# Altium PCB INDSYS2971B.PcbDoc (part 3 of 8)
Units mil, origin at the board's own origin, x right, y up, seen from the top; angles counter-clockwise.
Board outline 6450 x 5820 mil, 6 copper layers (Top Layer, Int1 (PGND), Int2 (AGND), Int3 (Signal), Int4 (PGND), Bottom Layer), stack 70.536 mil thick; 787 components, 431 nets, 2530 pads, 2497 vias.
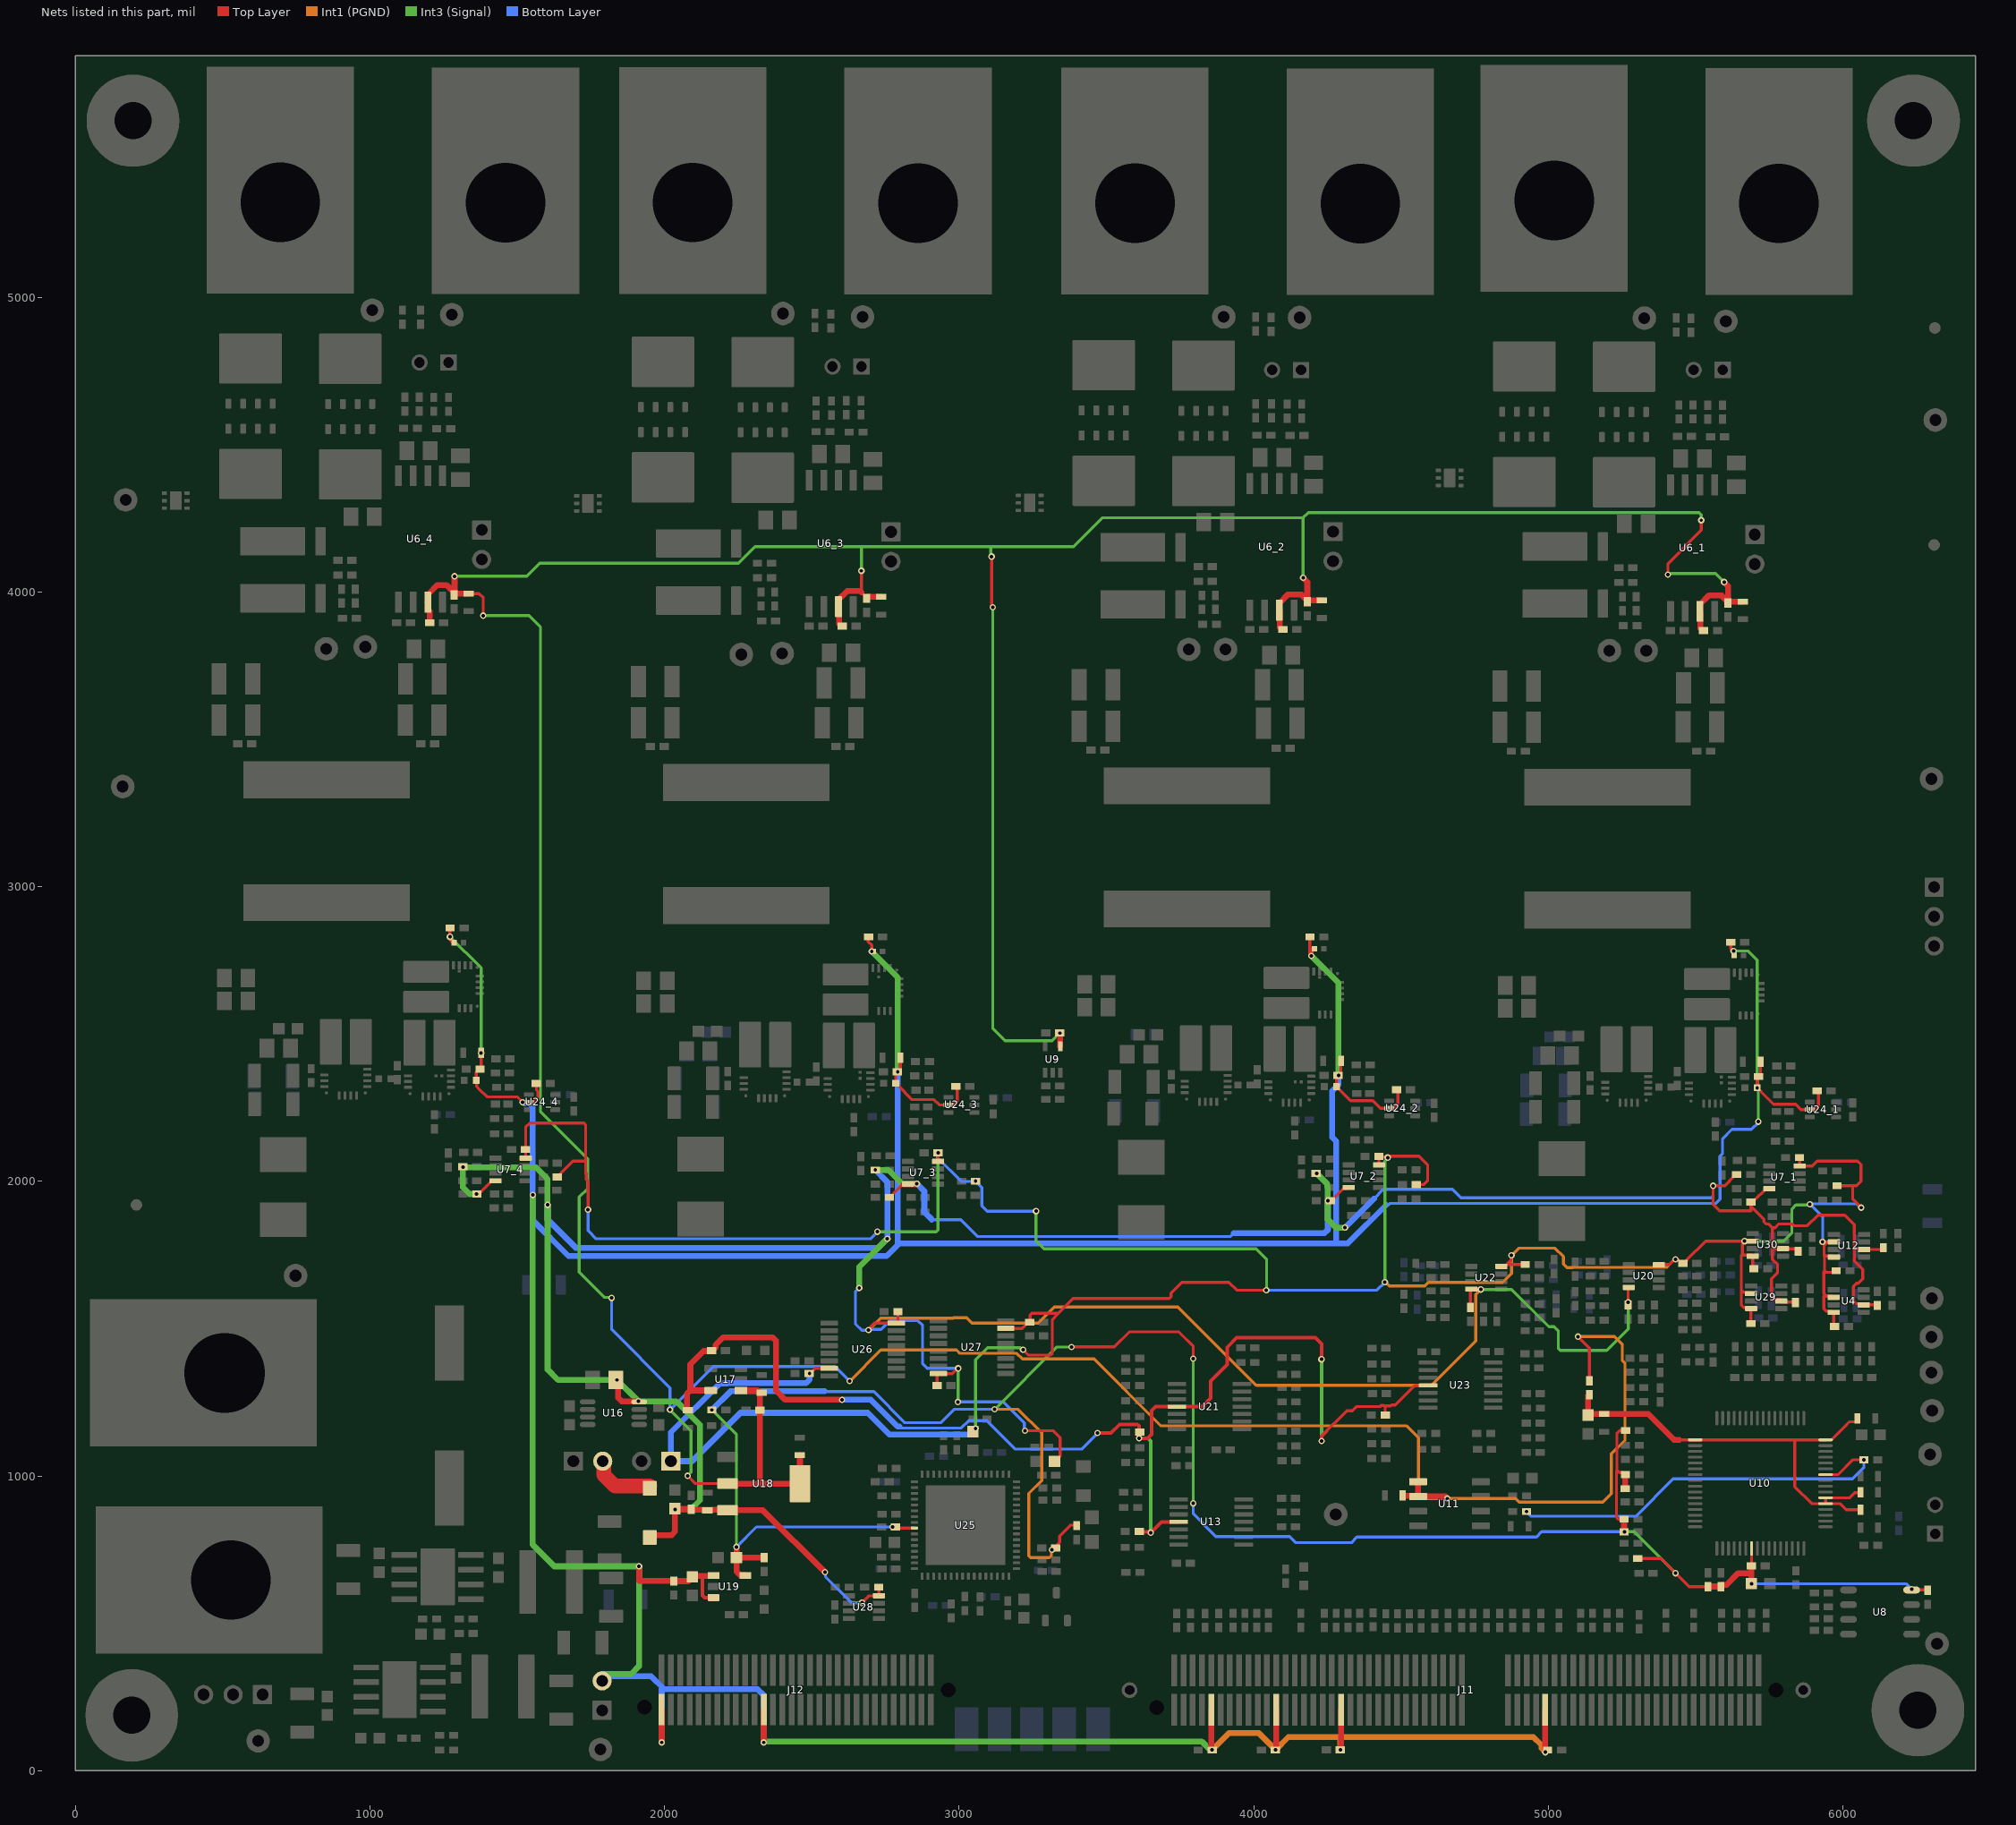
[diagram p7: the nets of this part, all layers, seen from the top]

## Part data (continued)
C41 C70 C95: library part CMP-0006644-2, "CAP, CERM, 0.015 uF, 16 V, +/- 10%, X7R, 0402", Cap_Case=0402, Manufacturer=MuRata, Supplier Part Number 1=490-1314-1-ND, TempCo=X7R, Tolerance_%=10%, Value1=Unknown, Value2=16V, ValueDisplayed=0.015uF
C42 C48 C49 C50 C51 C52 C53 C54 C110 C111 C112 C113: library part CMP-0006611-2, "CAP, CERM, 4700 pF, 25 V, +/- 10%, X5R, 0402", Cap_Case=0402, Manufacturer=MuRata, Supplier Part Number 1=GRM155R61E472KA01D-ND, TempCo=X5R, Tolerance_%=10%, Value1=Unknown, Value2=25V, ValueDisplayed=4700pF
C43 C56 C59 C63 C82 C86 C88 C92 C94 C116 C122: library part CMP-0007344-5, "CAP, CERM, 10 uF, 25 V, +/- 20%, X5R, 0603", Cap_Case=0603, Manufacturer=MuRata, Supplier Part Number 1=490-7202-1-ND, TempCo=X5R, Tolerance_%=20%, Value1=Unknown, Value2=25V, ValueDisplayed=10uF
C87: library part CMP-0076705-3, "CAP TANT POLY 2.2UF 10V 0603", Cap_Case=1.6x0.8x0.8mm, Manufacturer="KYOCERA AVX", TempCo=X7R, Tolerance_%=20%, Value2=10V, ValueDisplayed=2.2uF
D1 D2 D3: library part CMP-0002894-2, "LED, Green, SMD", Color=green, Manufacturer="Wurth Elektronik", Value1=W, Value2=2V
D4_1 D4_2 D4_3 D4_4 D5_1 D5_2 D5_3 D5_4: library part CMP-0028594-3, "Diode, Schottky, 40 V, 0.35 A, SOD-523", Manufacturer="Diodes Inc.", Value1=0.35A, Value2=0.65V
D6: library part CMP-0002829-3, "LED, Red, SMD", Color=red, Manufacturer=Lite-On, Value1=W, Value2=2V
D7: library part CMP-0082437-2, "LED, Blue, SMD", Color=Blue, Manufacturer=Lite-On, Power_TotalModule=76mW, Value1=0.076W, Value2=3.3V
F1_1 F1_2 F1_3 F1_4: library part CMP-0003569-2, "Fuse, 15 A, SMD", Irating_A=15A
FID1 FID2 FID3: library part CMP-0077181-1, "Fiducial mark.  There is nothing to buy or mount.", Manufacturer=N/A
H1 H2 H3 H4: library part CMP-0003617-1, "Machine Screw, Round, #4-40 x 1/4, Nylon, Philips panhead", Manufacturer="B&F Fastener Supply", Supplier Part Number 1=H542-ND
H5 H6 H7 H8: library part CMP-0003610-1, "Standoff, Hex, 0.5\"L #4-40 Nylon", Manufacturer=Keystone, Supplier Part Number 1=36-1902C-ND
J1 J2 J7_1 J7_2 J7_3 J7_4 J8_1 J8_2 J8_3 J8_4: library part CMP-0055387-2, "Standard Banana Jack, Uninsulated, 15A", Manufacturer="Cinch Connectivity", Supplier Part Number 1=J147-ND
J3 J10_1 J10_2 J10_3 J10_4: library part CMP-0075228-1, "Header (Shrouded), 2.5mm, 2x1, Tin, TH", Color=White, Current_A=3A, Manufacturer="JST Manufacturing", Supplier Part Number 1=455-1611-ND, Voltage_V=250V
J6 J16: library part CMP-0075484-1, "Header, 100mil, 3x1, Gold, TH", Manufacturer=Samtec, Supplier Part Number 1=HTSW-103-07-G-S-ND
J9_1 J9_2 J9_3 J9_4 J14 J15 J17: library part CMP-0075483-1, "Header, 100mil, 2x1, Gold, TH", Manufacturer=Samtec, Supplier Part Number 1=SAM8736-ND
J11: library part CMP-0003814-2, "C2000 controlCARD-120HSEC connector, SMT", Manufacturer=Samtec
J12: library part CMP-0003859-2, "C2000 controlCARD-180HSEC (60-pin addon) connector, SMT", Manufacturer=Samtec
L1_1 L1_2 L1_3 L1_4: library part CMP-0060973-1, "Inductor, Shielded, Composite, 1 uH, 57.5 A, 0.000929 ohm, SMD", Manufacturer=Coilcraft, Value1="0.000929 ohm", Value2=57.5A, ValueDisplayed=1uH
L2 L3: library part CMP-0095453-1, "22 µH Shielded Inductor 5.8 A 46.9mOhm Max Nonstandard", Digikey Part Number=2457-XGL6060-223MEC-ND, Manufacturer=Coilcraft, Operating Temperature Range=to, Self Resonant Frequency=9MHz, Test Frequency=1MHz, Tolerance_%=20%
L4: library part CMP-0003369-1, "Ferrite Bead, 1000 ohm @ 100 MHz, 1.5 A, 1806", Manufacturer=MuRata, Supplier Part Number 1=490-1061-1-ND, Value1="0.09 ohm", Value2=1.5A, ValueDisplayed="1000 ohm"
LBL1: library part CMP-0003625-1, "Thermal Transfer Printable Labels, 0.650\" W x 0.200\" H - 10,000 per roll", Manufacturer=Brady, Supplier Part Number 1=97C5133
Logo1: library part CMP-0074844-1
Logo2: library part CMP-0074838-1, "Texas Instrument Corporate Signature"
Logo3: library part CMP-0074847-1, "FCC_disclaimer"
Logo4: library part CMP-0074769-3, Manufacturer="Texas Instruments"
Logo5 Logo6 Logo7 Logo8: library part CMP-0074837-2, "IEC 61010-1 Hot Surface Warning", Manufacturer="Texas Instruments"
NT1_1 NT1_2 NT1_3 NT1_4 NT2_1 NT2_2 NT2_3 NT2_4: library part CMP-0078142-6, "Single point connection between nets.", Manufacturer=N/A
Q1_1 Q1_2 Q1_3 Q1_4 Q2_1 Q2_2 Q2_3 Q2_4 Q3_1 Q3_2 Q3_3 Q3_4 Q4_1 Q4_2 Q4_3 Q4_4: library part CMP-0000274-2, "MOSFET, N-CH, 25 V, 100 A, DNK0008A (VSON-CLIP-8)", Alternate Manufacturer=None, Manufacturer="Texas Instruments", Supplier Part Number 1=CSD16570Q5B-ND, Value1=0, Value2="192 nC"
Q5: library part CMP-0000769-1, "MOSFET, N-CH, 60 V, 0.17 A, SOT-23", Alternate Manufacturer=None, Manufacturer="Diodes Inc.", Supplier Part Number 1=2N7002-FDICT-ND, Value1=7, Value2="223 nC"
R1_1 R1_2 R1_3 R1_4 R9_1 R9_2 R9_3 R9_4 R14_1 R14_2 R14_3 R14_4: library part CMP-02407-004899-1, "RES Thick Film, 3.01Ω, 1%, 0.063W, 200ppm/°C, 0402", Case Code (Imperial)=0402, Case Code (Metric)=1005, Max Operating Temperature=155°C, Max Power Dissipation=63mW, Min Operating Temperature=-55°C, Package Quantity=10000, Resistance=3.01R, Temperature Coefficient=200ppm/°C, Tolerance=1%, Voltage Rating=50V
R2_1 R2_2 R2_3 R2_4: library part CMP-0086415-1, "RESISTOR - ISA-WELD SHUNT, 0.000", Manufacturer=Vishay, Power_W=9W, TempCo=75ppm/°C, Tolerance_%=1%
R3_1 R3_2 R3_3 R3_4: library part CMP-0020448-3, "RES, 10, 5%, 0.125 W, AEC-Q200 Grade 0, 0805", Manufacturer=Vishay-Dale, Power_W=125mW, Supplier Part Number 1=541-10ACT-ND, TempCo="200 ppm/C", Tolerance_%=5%, Value2=0.125W, Value_Code=10R0, ValueDisplayed=10
R4_1 R4_2 R4_3 R4_4 R5_1 R5_2 R5_3 R5_4 R17_1 R17_2 R17_3 R17_4 R18_1 R18_2 R18_3 R18_4 R20_1 R20_2 R20_3 R20_4 R21_1 R21_2 R21_3 R21_4: library part CMP-0081622-1, "RES, 1.00, 1%, 0.125 W, 0402", Manufacturer="Stackpole Electronics Inc", Power_W=125mW, Supplier Part Number 1=CSR0402FK1R00CT-ND, TempCo="200 ppm/C", Tolerance_%=1%, Value2=0.125W, Value_Code=1R00, ValueDisplayed=1.00
R6_1 R6_2 R6_3 R6_4 R7_1 R7_2 R7_3 R7_4: library part CMP-0020951-3, "RES, 1.00 k, 1%, 0.125 W, AEC-Q200 Grade 0, 0805", Manufacturer=Vishay-Dale, Power_W=125mW, Supplier Part Number 1=541-1.00KCCT-ND, TempCo="100 ppm/C", Tolerance_%=1%, Value2=0.125W, Value_Code=1k00, ValueDisplayed=1.00k
R8 R15_1 R15_2 R15_3 R15_4 R16 R19_1 R19_2 R19_3 R19_4 R22_1 R22_2 R22_3 R22_4 R36 R37 R38 R39 R40 R41 R42 R43 R44 R45 R46 R48 R50 R55 R56 R70 R88 R101 R106 R113 R117 R139 R151 R162 R175 R199 R200 R201 R202 R203 R204 R205 R206 R210 R211 R212 R213 R214 R215 R216 R218 R220 R223 R225 R227 R235 R236 R237 R238 R239 R240 R242 R244 R245 R246 R247 R248 R249 R252 R253 R255 R256 R257 R258 R259 R260: library part CMP-0026822-3, "RES, 0, 5%, 0.063 W, AEC-Q200 Grade 0, 0402", Manufacturer=Vishay-Dale, Power_W=63mW, Supplier Part Number 1=541-0.0JCT-ND, TempCo="200 ppm/C", Tolerance_%=5%, Value2=0.063W, Value_Code=0000, ValueDisplayed=0
R10_1 R10_2 R10_3 R10_4 R11_1 R11_2 R11_3 R11_4 R12_1 R12_2 R12_3 R12_4 R13_1 R13_2 R13_3 R13_4 R23_1 R23_2 R23_3 R23_4 R24_1 R24_2 R24_3 R24_4 R28_1 R28_2 R28_3 R28_4 R29_1 R29_2 R29_3 R29_4 R31_1 R31_2 R31_3 R31_4 R32_1 R32_2 R32_3 R32_4 R35_1 R35_2 R35_3 R35_4 R77 R79 R80 R82 R84 R89 R92 R99 R103 R104 R105 R108 R109 R110 R116 R127 R128 R177 R178 R183 R184 R185 R186 R191 R192 R221 R222 R224 R228 R230 R243 R254: library part CMP-0026796-1, "RES, 10.0 k, 0.1%, 0.063 W, 0402", Manufacturer="TT Electronics/IRC", Power_W=63mW, TempCo="10 ppm/C", Tolerance_%=0.1%, Value2=0.063W, Value_Code=10k0, ValueDisplayed=10.0k
R25_1 R25_2 R25_3 R25_4: library part CMP-0025963-3, "RES, 10.0, 1%, 0.063 W, AEC-Q200 Grade 0, 0402", Manufacturer=Vishay-Dale, Power_W=63mW, Supplier Part Number 1=541-10.0LCT-ND, TempCo="100 ppm/C", Tolerance_%=1%, Value2=0.063W, Value_Code=10R0, ValueDisplayed=10.0
R26_1 R26_2 R26_3 R26_4 R33_1 R33_2 R33_3 R33_4: library part CMP-0025992-3, "RES, 12.4 k, 1%, 0.063 W, AEC-Q200 Grade 0, 0402", Manufacturer=Vishay-Dale, Power_W=63mW, Supplier Part Number 1=541-12.4KLCT-ND, TempCo="100 ppm/C", Tolerance_%=1%, Value2=0.063W, Value_Code=12k4, ValueDisplayed=12.4k
R27_1 R27_2 R27_3 R27_4 R34_1 R34_2 R34_3 R34_4: library part CMP-0026745-1, "RES, 100 k, 1%, 0.063 W, 0402", Manufacturer="Samsung Electro-Mechanics", Power_W=63mW, Supplier Part Number 1=1276-3432-1-ND, TempCo="100 ppm/C", Tolerance_%=1%, Value2=0.063W, Value_Code=100k
R30_1 R30_2 R30_3 R30_4 R112 R114 R137 R143 R148 R154 R158 R165 R167 R176: library part CMP-0026162-2, "RES, 20.0 k, 1%, 0.063 W, AEC-Q200 Grade 0, 0402", Manufacturer=Vishay-Dale, Power_W=63mW, Supplier Part Number 1=541-20.0KLCT-ND, TempCo="100 ppm/C", Tolerance_%=1%, Value2=0.063W, Value_Code=20k0, ValueDisplayed=20.0k
R47 R49 R51 R52 R53 R54 R58 R59 R60 R61 R62 R63 R64 R65 R66 R67 R68 R69 R71 R72 R73 R74 R75 R111 R194 R195 R196 R197 R198 R208 R209 R217 R219 R226 R229 R233 R234: library part CMP-0026880-3, "RES, 22, 5%, 0.063 W, AEC-Q200 Grade 0, 0402", Manufacturer=Vishay-Dale, Power_W=63mW, Supplier Part Number 1=541-22JCT-ND, TempCo="200 ppm/C", Tolerance_%=5%, Value2=0.063W, Value_Code=22R0, ValueDisplayed=22
R57 R126 R131 R231 R232 R250 R251: library part CMP-0026770-1, "RES, 1.00 k, 0.1%, 0.063 W, 0402", Manufacturer=Panasonic, Power_W=63mW, Supplier Part Number 1=P1.0KDCCT-ND, TempCo="25 ppm/C", Tolerance_%=0.1%, Value2=0.063W, Value_Code=1k00, ValueDisplayed=1.00k
R76: library part CMP-0026833-3, "RES, 120, 5%, 0.063 W, AEC-Q200 Grade 0, 0402", Manufacturer=Vishay-Dale, Power_W=63mW, Supplier Part Number 1=541-120JCT-ND, TempCo="200 ppm/C", Tolerance_%=5%, Value2=0.063W, Value_Code=120R, ValueDisplayed=120
R78 R81 R83 R85 R86 R87 R90 R91 R93 R94 R95 R96 R97 R98 R100 R102 R133 R138 R144 R149 R155 R161 R166 R173: library part CMP-0026402-2, "RES, 499, 1%, 0.063 W, AEC-Q200 Grade 0, 0402", Manufacturer=Vishay-Dale, Power_W=63mW, Supplier Part Number 1=541-499LCT-ND, TempCo="100 ppm/C", Tolerance_%=1%, Value2=0.063W, Value_Code=499R, ValueDisplayed=499
R107: library part CMP-0026632-2, "RES, 0.22, 1%, 0.125 W, AEC-Q200 Grade 0, 0402", Manufacturer=Panasonic, Power_W=125mW, Supplier Part Number 1=P.22AKCT-ND, TempCo="250 ppm/C", Tolerance_%=1%, Value2=0.125W, Value_Code=R220, ValueDisplayed=0.22
R115: library part CMP-0026158-2, "RES, 200 k, 1%, 0.063 W, AEC-Q200 Grade 0, 0402", Manufacturer=Vishay-Dale, Power_W=63mW, Supplier Part Number 1=541-200KLCT-ND, TempCo="100 ppm/C", Tolerance_%=1%, Value2=0.063W, Value_Code=200k
R118 R179 R180 R181 R182 R187 R188 R189 R190: library part CMP-0026367-2, "RES, 40.2 k, 1%, 0.063 W, AEC-Q200 Grade 0, 0402", Manufacturer=Vishay-Dale, Power_W=63mW, Supplier Part Number 1=541-40.2KLCT-ND, TempCo="100 ppm/C", Tolerance_%=1%, Value2=0.063W, Value_Code=40k2, ValueDisplayed=40.2k
R119: library part CMP-0026720-1, "RES, 69.8 k, 1%, 0.063 W, 0402", Manufacturer=Rohm, Power_W=63mW, TempCo="100 ppm/C", Tolerance_%=1%, Value2=0.063W, Value_Code=69k8, ValueDisplayed=69.8k
R120 R121: library part CMP-0026721-1, "RES, 100 k, 1%, 0.0625 W, 0402", Manufacturer="Yageo America", Power_W=62.5mW, Supplier Part Number 1=311-100KLRCT-ND, TempCo="100 ppm/C", Tolerance_%=1%, Value2=0.0625W, Value_Code=100k
R122 R123: library part CMP-0078779-1, "RES, 10.0 k, 1%, 0.2 W, AEC-Q200 Grade 0, 0402", Manufacturer=Panasonic, Power_W=200mW, Supplier Part Number 1=P17230CT-ND, TempCo="100 ppm/C", Tolerance_%=1%, Value2=0.2W, Value_Code=10k0, ValueDisplayed=10.0k
R124 R125: library part CMP-0022957-5, "RES, 26.1 k, 1%, 0.1 W, 0603", Manufacturer=Yageo, Power_W=100mW, Supplier Part Number 1=311-26.1KHRCT-ND, TempCo="100 ppm/C", Tolerance_%=1%, Value2=0.1W, Value_Code=26k1, ValueDisplayed=26.1k
R129 R130 R132: library part CMP-0094724-1, "Jumper 0.25W, 1/4W Chip Resistor 1206 (3216 Metric) - Thick Film", Digikey Part Number=541-4170-1-ND, Manufacturer=Vishay, Mouser Part Number=71-CRCW12060000Z0EAC, Operating Temperature Range="-55°C to +155°C", Power_W=250mW
R134 R141 R145 R150 R156 R164 R168 R174: library part CMP-0026371-2, "RES, 41.2 k, 1%, 0.063 W, AEC-Q200 Grade 0, 0402", Manufacturer=Vishay-Dale, Power_W=63mW, Supplier Part Number 1=541-41.2KLCT-ND, TempCo="100 ppm/C", Tolerance_%=1%, Value2=0.063W, Value_Code=41k2, ValueDisplayed=41.2k
R135 R136 R140 R142 R146 R147 R152 R153 R157 R159 R160 R163 R169 R170 R171 R172: library part CMP-0026403-2, "RES, 49.9 k, 1%, 0.063 W, AEC-Q200 Grade 0, 0402", Manufacturer=Vishay-Dale, Power_W=63mW, Supplier Part Number 1=541-49.9KLCT-ND, TempCo="100 ppm/C", Tolerance_%=1%, Value2=0.063W, Value_Code=49k9, ValueDisplayed=49.9k
R193_1 R193_2 R193_3 R193_4: library part CMP-0026057-3, "RES, 187, 1%, 0.063 W, AEC-Q200 Grade 0, 0402", Manufacturer=Vishay-Dale, Power_W=63mW, Supplier Part Number 1=541-187LCT-ND, TempCo="100 ppm/C", Tolerance_%=1%, Value2=0.063W, Value_Code=187R, ValueDisplayed=187
R207 R241: library part CMP-0025743-4, "RES, 1.0, 5%, 0.1 W, AEC-Q200 Grade 0, 0603", Manufacturer=Vishay-Dale, Power_W=100mW, Supplier Part Number 1=541-1.0GCT-ND, TempCo="200 ppm/C", Tolerance_%=5%, Value2=0.1W, Value_Code=1R00, ValueDisplayed=1.0
SH-J2 SH-J3 SH-J4 SH-J5: library part CMP-0003761-2, "Shunt, 2.54mm, Gold, Black", Manufacturer="Wurth Elektronik", Supplier Part Number 1=732-2678-ND
T1 T2 T3_1 T3_2 T3_3 T3_4 T4_1 T4_2 T4_3 T4_4: library part CMP-0075010-2, "Terminal 70A Lug", Manufacturer=Panduit, Supplier Part Number 1=CXS70-14-C-ND
TP1 TP3_1 TP3_2 TP3_3 TP3_4 TP5_1 TP5_2 TP5_3 TP5_4 TP11: library part CMP-0055137-2, "Test Point, Miniature, Red, TH", Color=Red, Manufacturer="Keystone Electronics", Supplier Part Number 1=36-5000-ND
TP2 TP4_1 TP4_2 TP4_3 TP4_4 TP6_1 TP6_2 TP6_3 TP6_4 TP9 TP10 TP12 TP13 TP14 TP15 TP16 TP17 TP23: library part CMP-0055138-2, "Test Point, Miniature, Black, TH", Color=Black, Manufacturer="Keystone Electronics", Supplier Part Number 1=36-5001-ND
TP7 TP8 TP20 TP21 TP22: library part CMP-0055162-1, "Test Point, Miniature, SMT", Manufacturer=Keystone, Supplier Part Number 1=36-5019TR-ND
TP18 TP19: library part CMP-0055154-1, "Test Point, Miniature, Blue, TH", Color=Blue, Manufacturer=Keystone, Supplier Part Number 1=36-5117-ND
U1_1 U1_2 U1_3 U1_4 U2_1 U2_2 U2_3 U2_4 U3_1 U3_2 U3_3 U3_4: library part CMP-0037654-1, "100-V, 64-A GaN with Integrated Driver", Manufacturer="Texas Instruments", Max Supply Voltage=5.25V, Min Supply Voltage=4.75V, Nominal Supply Current=3mA, Operating Temperature Range="-40°C to +125°C"
U4 U12 U29 U30: library part CMP-0093651-2, "-4-V to 110-V, Bidirectional, Ultra-Precise Current Sense Amplifier With Enhanced PWM Rejection", Input Bias Current=40uA, Input Offset Voltage=0.002mV, Manufacturer="Texas Instruments", Max Supply Voltage=20V, Min Supply Voltage=2.7V, Nominal Supply Current=2.5mA, Operating Temperature Range="-40°C to +125°C", Voltage Gain=0.2V/mV
U5_1 U5_2 U5_3 U5_4: library part CMP-0077837-1, "5-V Precision Surge Protection Clamp, DRV0006A (WSON-6)", Alternate Manufacturer="Texas Instruments"
U6_1 U6_2 U6_3 U6_4: library part CMP-0095182-3, "Isolated Switch Driver With Integrated 10-V Gate Supply SOIC8", Manufacturer="Texas Instruments", Max Power Dissipation=350mW, Max Supply Voltage=5.5V, Min Supply Voltage=3V, Nominal Supply Current=4-33mA, Operating Temperature Range="-40°C to +150°C", Output Voltage=10V
U7_1 U7_2 U7_3 U7_4: library part CMP-0089113-1, "Dual Comparator SOT23-8", Input Bias Current=-0.0035uA, Input Offset Voltage=0.37mV, Manufacturer="Texas Instruments", Max Supply Voltage=36V, Min Supply Voltage=3V, Nominal Supply Current=400-550uA, Operating Temperature Range="-40°C to +85°C", Output Current Per Channel=21mA, Voltage Gain=200V/mV
U8: library part CMP-0065059-3, "3.3-V to 5-V RS-485 Transceivers with Auto-direction Control / and ±12-kV IEC ESD Protection", Alternate Manufacturer="Texas Instruments", Alternate PartNumber=THVD1426DR, Operating Temperature Range="-40 to 125 C"
U9: library part CMP-0013250-3, "TMP235DCK, DCK0005A (SOT-5)", Manufacturer="Texas Instruments"
U10: library part CMP-0075962-3, "16-Bit High-Speed 8-Channel Simultaneous-Sampling ADC With Bipolar Inputs on a Single Supply, PM0064A (LQFP-64)", Alternate Manufacturer="Texas Instruments", Alternate PartNumber=ADS8588SIPM, Operating Temperature Range="-40 to 125 C", Rating=Catalog
U11: library part CMP-0095913-1, "0.5 ppm/°C Maximum Drift, 0.1 ppmp-p 1/f Noise, 350 μA current, Precision Voltage Reference", Manufacturer="Texas Instruments", Operating Temperature Range=to
U13 U21 U23: library part CMP-0120501-1, "Quad, 36-V, 1.2-MHz 3-mV offset voltage operational amplifier", Digikey Part Number=296-LM324BIPWRCT-ND, Input Bias Current=-0.01uA, Input Offset Voltage=0.6mV, Manufacturer="Texas Instruments", Max Dual Supply Voltage=18V, Max Supply Voltage=36V, Min Dual Supply Voltage=2.5V, Min Supply Voltage=5V, Mouser Part Number=595-LM324BIPWR, Nominal Supply Current=240-350uA, Operating Temperature Range="-40°C to +85°C", Output Current Per Channel=20mA, Voltage Gain=100V/mV
U14 U15: library part CMP-0096892-1, "4.2-V to 80-V, 1-A Synchronous Buck Converter with 40-µA IQ", Manufacturer="Texas Instruments", Max Supply Voltage=80V, Min Supply Voltage=4.2V, Mouser Part Number=595-LMR38010FDDAR, Nominal Supply Current=40uA, Operating Temperature Range="-40°C to +150°C", Output Voltage=1-75V, Switching Frequency=200-2200kHz
U16: library part CMP-0041281-2, "CMOS Voltage Converter, DGK0008A (VSSOP-8)", Manufacturer="Texas Instruments", Total Supply Voltage(Max)(+5V is 5, +/-5V is 10)=10, Total Supply Voltage(Min)(+5V is 5, +/-5V is 10)=1.5
U17: library part CMP-0092532-1, "300-mA, Ultra-Low-Noise, Low-IQ, High PSRR LDO", Digikey Part Number=296-TPS7A2033PDBVRCT-ND, Dropout Voltage=145mV, Manufacturer="Texas Instruments", Max Supply Voltage=6V, Min Supply Voltage=1.6V, Mouser Part Number=595-TPS7A2033PDBVR, Nominal Supply Current=6.5uA, Operating Temperature Range="-40°C to +125°C", Output Voltage=3.3V
U18: library part CMP-0036758-1, "Single Output LDO, 1 A, Fixed 5 V Output, 2 to 5.5 V Input, 4-pin SOT-223 (DCY), -40 to 125 degC, Green (RoHS & no Sb/Br)", Manufacturer="Texas Instruments", PartNumber=TLV1117-50IDCY
U19: library part CMP-0036866-2, "Single Output Low Noise LDO, 400 mA, Fixed 3.3 V Output, 1.7 to 5.5 V Input, with Reverse Current Protection, 5-pin SOT-23 (DBV), -40 to 85 degC, Green (RoHS & no Sb/Br)", Alternate Manufacturer="Texas Instruments", Alternate PartNumber=TPS73633DBVT, Rating=Catalog
U20 U22 U28: library part CMP-0098326-1, "Precision, Rail-to-Rail Input and Output, 24-V, Zero-Drift Operational Amplifiers", Digikey Part Number=296-OPA2186DDFRCT-ND, Input Bias Current=0.000005uA, Input Offset Voltage=0.001mV, Manufacturer="Texas Instruments", Max Dual Supply Voltage=12V, Max Supply Voltage=24V, Min Dual Supply Voltage=2.25V, Min Supply Voltage=4.5V, Mouser Part Number=595-OPA2186DDFR, Nominal Supply Current=90uA, Operating Temperature Range="-40°C to +125°C", Output Current Per Channel=20mA, Voltage Gain=148dB
U24_1 U24_2 U24_3 U24_4: library part CMP-0051909-3, "Dual Buffer Gate, DCK0006A (SOT-SC70-6)", F @ Nom Voltage(Max)(Mhz)=150, Generic Part Number=SN74LVC2G34, ICC @ Nom Voltage(Max)(mA)=0.01, Manufacturer="Texas Instruments", Operating Temperature Range="-40 to 125,-40 to 85 C", Rating=Catalog, tpd @ Nom Voltage(Max)(ns)=8.6,4.4,4.1,3.2, Voltage(Nom)(V)=1.8,2.5,3.3,5
U25: library part CMP-0049649-2, "16-Bit, Quad-Channel, Software-Configurable Universal Analog Frontend", Manufacturer="Texas Instruments", Max Supply Voltage=36V, Min Supply Voltage=1.71V, Operating Temperature Range="-40°C to +125°C"
U26 U27: library part CMP-0043042-1, "+/-12-V, 2:1, 3-channel multiplexer with 1.8-V logic compatible logic", Digikey Part Number=296-TMUX4053PWRCT-ND, Manufacturer="Texas Instruments", Max Supply Voltage=24V, Min Supply Voltage=5V, Mouser Part Number=595-TMUX4053PWR, On State Resistance=60Ω, Operating Temperature Range="-55°C to +125°C"
ZZ1: library part CMP-0003616-3
ZZ2: library part CMP-0077236-1
ZZ3: library part CMP-0077237-1
ZZ4: library part CMP-0077238-1

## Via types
v1: diameter 22, hole 12.5, Top Layer to Bottom Layer, 873 vias
v2: diameter 22, hole 12, Top Layer to Bottom Layer, tented both sides, 788 vias
v3: diameter 22, hole 12, Top Layer to Bottom Layer, 586 vias
v4: diameter 22, hole 12.5, Top Layer to Bottom Layer, tented both sides, 249 vias
v5: diameter 24, hole 12, Top Layer to Bottom Layer, tented both sides, 1 vias

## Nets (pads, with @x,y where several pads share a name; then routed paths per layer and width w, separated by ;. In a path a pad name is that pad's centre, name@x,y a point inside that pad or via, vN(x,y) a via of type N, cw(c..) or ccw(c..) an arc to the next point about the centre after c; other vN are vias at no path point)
3V3A: C69.1 C85.1 C96.2 C109.2 R126.2 U13.4 U17.5 U21.4 U23.4 | length 4358.6
  Top Layer w10: 4247.11,1152.27 4301.19,1206.35 4316.34,1221.5 4334.55,1221.5 4348.57,1235.52 4428.37,1235.52 4432.39,1239.55 4440.68,1239.55 4446.54,1233.69 ; C109.2@4446.54,1206.64 4446.54,1233.69 ; U23.4@4592.31,1308.02 4590.42,1306.13 4545.82,1306.13 4480.26,1240.57 4467.73,1240.57 4464.81,1237.65 4448.07,1237.65 4446.54,1236.11 4446.54,1233.69
  Top Layer w12: v2(3469.76,1146.27) 3515.52,1146.27 3544.7,1175.45 3605.53,1175.45 3610.59,1170.39 v2(3610.59,1128.4) 3639.46,1128.4 3653.14,1142.07 3653.14,1221.57 3667.09,1235.52 U21.4@3739.49,1235.52 3824.49,1235.52 3853.8,1264.83 3853.8,1321.82 3910.26,1378.28 3910.26,1436.85 3942.47,1469.07 4209.83,1469.07 4230,1448.9 v2(4230,1396.1) ; C69.1@3611.06,812.17 3613.39,809.85 3648.09,809.85 v2(3650,807.93) 3650.68,807.93 3686.76,844.02 U13.4@3745.47,844.02 ; v2(4230.36,1119.02) 4230.62,1119.27 4230.62,1135.78 4247.11,1152.27
  Top Layer w20: C85.1@2070.75,1223.45 2075.52,1223.45 2075.52,1278.65 2087.24,1290.37 ; U17.5@2156.44,1290.37 2087.24,1290.37 ; v2(2602.58,1258.62) 2409.75,1258.62 2378,1290.37 2378,1458.95 2366.28,1470.67 2198.75,1470.67 2173.12,1445.04 2173.12,1435.51 2163.43,1425.82 R126.2@2159.49,1425.82 2157.68,1424.01 2132.07,1424.01 2087.24,1379.18 2087.24,1290.37
  Int3 (Signal) w12: v2(3610.59,1128.4) 3640.9,1128.4 3650,1119.29 v2(3650,807.93) ; v2(4230,1396.1) 4230,1119.38 v2(4230.36,1119.02)
  Bottom Layer w10: 2796.56,1168.02 2801.56,1163.02 3007.52,1163.02 3032.52,1188.02 3093.62,1188.02 3190.4,1091.24 3415.28,1091.24 v2@3469.63,1145.6
  Bottom Layer w20: v2(2602.58,1258.62) 2700.27,1258.62 2790.87,1168.02 2796.56,1168.02
3V3D: C39.2 C55.1 C56.1 C94.1 C123.2 R79.2 R82.2 R84.2 R89.2 R92.1 R103.2 R104.2 R105.2 R128.1 R131.2 R228.2 R231.2 U8.8 U10.23 U19.5 U25.9 | length 8031.1
  Top Layer w10: C123.2@2783.62,827.03 2787.28,823.37 2848.03,823.37 U25.9@2848.31,823.09 ; v2(3315.11,749.63) 3340.82,775.34 3340.82,796.34 3377.41,832.93 3397.74,832.93 R228.2@3399.11,831.55 R228.2@3399.11,829.66 ; v2(3381.16,1437.92) 3381.85,1438.61 3527.15,1438.61 3577.9,1489.36 3745.21,1489.36 3794.68,1439.9 v2(3794.68,1398.15) ; R79.2@5257.32,853.61 5237.59,853.61 5231.73,859.47 5231.73,1017.93 5233.31,1019.5 ; R104.2@5261.56,1004.18 5254.37,1011.37 5241.44,1011.37 5233.31,1019.5 ; R105.2@5262.52,1154.56 5242.79,1154.56 5233.31,1145.08 5233.31,1019.5 ; R89.2@5303.62,720.14 5382.34,720.14 v2(5432.34,670.14) 5478.32,624.17 R84.2@5541.97,624.17 ; C55.1@5689.53,694.56 5690.47,695.5 U10.23@5690.47,753.69 ; v2(6233.6,615.41) 6235.79,613.22 6286.42,613.22 C39.2@6288,611.64
  Top Layer w20: v2(2243.93,759.11) 2243.93,675.64 2255.64,663.92 2272.49,663.92 U19.5@2274.31,662.11 ; C94.1@2251.05,722.9 R131.2@2338.06,722.9 ; R82.2@5257.32,810.7 R79.2@5257.32,853.61 ; R103.2@5261.18,956.69 5261.56,957.06 R104.2@5261.56,1004.18 ; R84.2@5541.97,624.17 5542.94,625.14 R92.1@5585.98,625.14 ; R92.1@5585.98,624.17 R92.1@5585.98,625.14 ; C55.1@5689.53,694.56 5689.53,670.14 ; v2(5689.91,634.43) v2(5689.91,634.43) C56.1@5689.53,634.48 5689.53,670.14 ; R92.1@5585.98,625.14 5585.98,628.11 5587.79,629.92 5604.77,629.92 5645,670.14 5689.53,670.14
  Int3 (Signal) w10: v2@2152.89,1227 v2@2160.38,1227 ; v2(2160.38,1224.34) 2243.93,1140.79 v2(2243.93,759.11) ; v2(3120.41,1226.31) 3332.02,1437.92 v2(3381.16,1437.92) ; v2(3794.68,906.98) v2(3794.68,1398.15) ; v2(5259.29,810.7) 5291.79,810.7 v2(5432.34,670.14)
  Int1 (PGND) w10: v2(3120.41,1226.31) 3200.62,1226.31 3280.49,1146.45 3280.49,984.68 3236.76,940.95 3236.76,891.77 3236.02,891.03 3236.02,729.14 3241.88,723.28 3307,723.28 3312.86,729.14 3312.86,747.38 v2(3315.11,749.63) ; v2@3312.19,752.55 3316.97,757.34 v2@3317.45,757.34
  Bottom Layer w10: v2(2243.93,759.11) 2311.84,827.03 v2(2773.78,827.03) ; 2544.18,1287.5 2544.89,1286.78 2710.15,1286.78 2816.04,1180.89 2937.26,1180.89 2982.68,1226.31 v2(3120.41,1226.31) ; v2(3794.68,906.98) 3794.68,871.53 3871.65,794.55 4122.26,794.55 4143.07,773.75 4331.29,773.75 4350.38,792.84 4959.83,792.84 4977.69,810.7 v2(5259.29,810.7) ; v2(5689.91,634.43) 6214.58,634.43 v2(6233.6,615.41)
  Bottom Layer w20: v2(2160.38,1224.34) 2223.54,1287.5 2544.18,1287.5
5VA: C30_1.2 C30_2.2 C30_3.2 C30_4.2 C31_1.2 C31_2.2 C31_3.2 C31_4.2 C40.2 C60.1 C84.1 C87.1 R23_1.1 R23_2.1 R23_3.1 R23_4.1 R88.1 R127.2 U6_1.3 U6_2.3 U6_3.3 U6_4.3 U9.4 U11.1 U11.2 U17.1 U18.2 U18.4 | length 17418.3
  Top Layer w10: C30_4.2@1335,3995.03 1370.09,3995.03 1384.15,3980.97 1384.15,3920.43 v2(1383.91,3920.19) ; v2(2078.19,1000.89) 2104.85,974.23 U18.2@2213.31,974.23 ; v2(2668.21,4072.32) 2668.21,3999.86 2678.58,3989.48 C31_3.2@2685.39,3982.67 ; v2(3110,4120.75) 3110,3949.36 3114.18,3945.19 v2(3114.18,3948.73) ; v2(5100.56,1473.14) 5139.95,1433.76 R88.1@5139.95,1322.64 ; v2(5406.5,4059.51) 5406.5,4097.32 5519.39,4210.21 v2(5519.39,4244.02)
  Top Layer w20: U6_4.3@1194.29,3965.85 1197.91,3969.47 1197.91,3993.41 1228.6,4024.1 1259.2,4024.1 1283.19,4000.1 1283.19,3995.81 1285,3994 C31_4.2@1285,3990.06 ; U6_4.3@1196.1,3965.85 1196.1,3942.22 1202.48,3935.85 R23_4.1@1202.48,3896.44 ; v2(1286.81,4054.02) 1286.81,3995.03 C30_4.2@1335,3995.03 ; U18.2@2213.31,974.23 2322.67,974.23 2323.8,975.35 R127.2@2323.8,1223.45 C84.1@2323.8,1282.77 ; U17.1@2258.8,1290.37 2315.08,1290.37 2322.67,1282.77 C84.1@2323.8,1282.77 ; 2323.8,974.23 U18.4@2459.37,974.23 C87.1@2459.37,1070.25 ; C84.1@2330.17,1282.77 C84.1@2323.8,1282.77 ; R23_3.1@2602.87,3885.11 2598.93,3885.11 2592.2,3891.84 2592.2,3948.73 U6_3.3@2590.39,3950.55 2590.39,3974.17 2620.08,4003.85 2664.21,4003.85 2668.21,3999.86 ; C31_3.2@2685.39,3982.67 2686.42,3983.7 C30_3.2@2735.39,3983.7 ; v2(3341.61,2503.23) 3342.11,2502.74 3342.11,2459 U9.4@3343.09,2458.01 ; R23_2.1@4099.48,3873.5 4095.54,3873.5 4088.81,3880.23 4088.81,3937.13 U6_2.3@4087,3938.94 4087,3962.56 4116.69,3992.24 4160.82,3992.24 C31_2.2@4182,3971.06 ; v2(4167.72,4049.02) 4167.72,4048.48 4182,4034.2 C31_2.2@4182,3971.06 ; C31_2.2@4182,3967.13 C31_2.2@4182,3971.06 ; C30_2.2@4232,3972.09 4183.03,3972.09 C31_2.2@4182,3971.06 ; C60.1@4505.55,934.59 4505.55,932.5 4556.34,932.5 U11.2@4558.15,930.69 ; U11.1@4558.15,980.69 U11.2@4558.15,930.69 ; v2(4657.15,923.57) 4650.03,930.69 U11.2@4558.15,930.69 ; R23_1.1@5527.48,3869.5 5523.54,3869.5 5516.81,3876.23 5516.81,3933.13 U6_1.3@5515,3934.94 5515,3958.56 5544.69,3988.24 5588.82,3988.24 C31_1.2@5610,3967.06 ; v2(5597.09,4034.02) 5597.09,4033.48 5610,4020.56 C31_1.2@5610,3967.06 ; C31_1.2@5610,3963.13 C31_1.2@5610,3967.06 ; C30_1.2@5660,3968.09 5611.03,3968.09 C31_1.2@5610,3967.06
  Int3 (Signal) w10: v2(1286.81,4054.02) 1532.72,4054.02 1576.58,4097.89 2250.92,4097.89 2307.42,4154.39 2665.18,4154.39 ; v2(1383.91,3920.19) 1539.79,3920.19 1578.15,3881.83 1578.15,2236.72 1738.28,2076.58 1738.28,1975.06 1710,1946.78 1710,1691.76 1795.18,1606.58 1817.7,1606.58 v2(1820,1604.28) ; v2(2018.24,1224.67) 2090,1152.91 2090,1012.74 v2@2078.19,1000.93 ; v2(2668.21,4072.32) 2668.21,4151.37 2665.18,4154.39 ; v2(3110,4120.75) 3107.7,4123.05 3107.7,4154.39 ; v2(3114.18,3948.73) 3114.18,2518.07 3155.22,2477.02 3315.41,2477.02 v2(3341.61,2503.23) ; v2(4167.72,4049.02) 4167.72,4252.56 ; v2(5406.5,4059.51) 5410.12,4063.14 5567.97,4063.14 v2(5597.09,4034.02) ; v2(5519.39,4244.02) 5519.39,4262.74 5511.99,4270.14 4185.3,4270.14 4167.72,4252.56 ; 2665.18,4154.39 3107.7,4154.39 ; 3107.7,4154.39 3388.35,4154.39 3486.52,4252.56 4167.72,4252.56
  Int1 (PGND) w10: v2(2628.17,1321.86) 2734.3,1427.98 2991.1,1427.98 3002.95,1416.13 3195.57,1416.13 3214.66,1397.04 3458.39,1397.04 3685.28,1170.14 4519.46,1170.14 4559.77,1129.84 4559.77,945.3 4581.49,923.57 v2(4657.15,923.57) 4888.84,923.57 4901.45,910.96 5185.22,910.96 5214.35,940.09 5214.35,1075.57 5260.54,1121.77 5260.54,1382.57 5251.43,1391.69 5251.43,1446.38 5224.66,1473.14 v2(5100.56,1473.14)
  Bottom Layer w10: v2(1820,1604.28) 1820,1497.25 2018.24,1299 v2(2018.24,1224.67) 2165.14,1371.56 2578.46,1371.56 v2(2628.17,1321.86)
5VA_LN: C43.1 C44.1 C45.1 C46.1 C47.1 R88.2 U10.1 U10.37 U10.38 U10.48 | length 1593.2
  Top Layer w10: 5445,1122.78 U10.1@5498.54,1122.78 5836.59,1122.78 ; U10.48@5941.46,1122.78 5836.59,1122.78 ; U10.48@5961.06,1122.86 6004.93,1166.72 6022.25,1184.05 6045,1184.05 6050,1189.05 C47.1@6050,1195.14 ; C46.1@6060,885.14 6011.23,885.14 5990.13,906.25 U10.37@5941.46,906.25 ; C45.1@6060,945.14 6057.78,942.92 6040.86,942.92 6023.87,925.93 U10.38@5941.46,925.93 U10.37@5941.46,906.25 ; 5836.59,1122.78 5836.59,963.56 5893.9,906.25 U10.37@5941.46,906.25
  Top Layer w20: R88.2@5135,1272 C43.1@5135,1206.64 5138.5,1210.14 C44.1@5190,1210.14 5340,1210.14 5427.36,1122.78 5445,1122.78
5VD: C19_1.1 C19_2.1 C19_3.1 C19_4.1 C20_1.2 C20_2.2 C20_3.2 C20_4.2 C24_1.2 C24_2.2 C24_3.2 C24_4.2 C35.2 C36.2 C37.2 C38.2 C92.1 C93.2 C115_1.2 C115_2.2 C115_3.2 C115_4.2 J11.48 J11.84 J11.98 J11.112 J12.158 J12.180 J14.2 R9_1.1 R9_2.1 R9_3.1 R9_4.1 R14_1.1 R14_2.1 R14_3.1 R14_4.1 U19.1 U19.3 U24_1.5 U24_2.5 U24_3.5 U24_4.5 | length 16847.1
  Top Layer w10: C24_4.2@1271.71,2860.14 1271.16,2859.6 v2(1271.16,2830.14) 1273.46,2827.85 1273.46,2817.19 R14_4.1@1280.5,2810.14 ; R14_4.1@1281.49,2810.14 R14_4.1@1285.34,2810.14 ; v2(1377,2436.01) 1377,2384.6 C20_4.2@1373.39,2380.98 1369.45,2380.98 1360.63,2372.16 R9_4.1@1360.63,2342.64 1362.16,2341.12 1362.16,2321.69 1371.67,2312.17 1371.67,2312 1396.7,2286.97 1499.45,2286.97 v2(1517.6,2268.82) 1555.81,2268.82 1569.09,2282.09 1569.09,2306.56 1564.64,2311.01 C115_4.2@1564.64,2332.2 ; C24_3.2@2692.38,2830.14 2691.47,2829.24 2691.47,2813.49 2703.17,2801.8 v2(2703.17,2780.14) ; C20_3.2@2784.64,2366.45 R9_3.1@2784.64,2333.25 2815.8,2302.1 2815.8,2301.92 2840.15,2277.58 2914.98,2277.58 2933.03,2259.52 U24_3.5@2963.49,2259.52 2966.37,2262.4 2982.44,2262.4 2993.1,2273.06 2993.1,2318.13 C115_3.2@2988.42,2322.81 ; C20_3.2@2800.26,2378.4 C19_3.1@2800.26,2419.93 ; v2@4190.47,2770.64 4190.47,2829.65 C24_2.2@4190.97,2830.14 ; v2(4195.72,2765.39) 4198.02,2767.69 4198.02,2786.7 R14_2.1@4201.46,2790.14 ; C20_2.2@4281.25,2354.85 R9_2.1@4281.25,2321.64 4288.06,2314.83 4288.06,2314.66 4329.2,2273.53 4404.03,2273.53 4429.64,2247.91 U24_2.5@4460.1,2247.91 4462.98,2250.79 4479.05,2250.79 4489.71,2261.45 4489.71,2306.52 C115_2.2@4485.03,2311.2 ; C20_2.2@4296.12,2366.79 C19_2.1@4296.12,2408.88 ; C24_1.2@5619.94,2811.46 5619.36,2810.88 5619.36,2789.8 5626.96,2782.21 v2(5628.93,2782.21) 5630.25,2780.89 5630.25,2767.77 R14_1.1@5631.56,2766.46 ; C19_1.1@5720.66,2406.14 5720.66,2362.79 5724.42,2362.79 5717.61,2355.98 C20_1.2@5714.39,2355.98 5709.25,2350.85 v2(5709.25,2317.64) 5740.41,2286.49 5740.41,2286.31 5764.75,2261.97 5839.58,2261.97 5857.64,2243.91 U24_1.5@5888.1,2243.91 5890.98,2246.79 5907.05,2246.79 5917.71,2257.45 5917.71,2302.52 C115_1.2@5913.03,2307.2
  Top Layer w12: 2124.2,660.3 2128.35,656.14 2128.35,594.34 2135.38,587.31 U19.3@2166.04,587.31
  Top Layer w20: v2(1913.04,693.4) 1913.04,645.75 1915.21,643.58 2030.99,643.58 C93.2@2031.2,643.37 2080.84,643.37 2094.19,656.72 C92.1@2094.19,657.7 2096.79,660.3 2124.2,660.3 2164.23,660.3 U19.1@2166.04,662.11 ; v2(1989.99,95.71) J12.180@1989.99,207.15 ; v2(2336.34,95.6) 2336.45,95.71 J12.158@2336.45,207.15 ; J11.112@3855.98,206.29 3855.98,71.96 3857.8,70.14 v2(3858.62,70.14) ; v2(4074.12,70.64) 4075.15,70.64 4076.46,71.96 J11.98@4076.46,206.29 ; C36.2@4293.62,70.64 v2(4294.37,70.64) 4295.12,70.64 4296.93,72.46 J11.84@4296.93,206.29 ; v2(4989.84,62.4) 4989.84,62.94 4991.97,65.06 4991.97,68.33 4993.78,70.14 C37.2@4997.72,70.14 ; C37.2@4989.84,74.08 J11.48@4989.84,206.29
  Int3 (Signal) w10: v2(1271.16,2830.14) 1377,2724.3 v2(1377,2436.01) ; v2(5628.93,2782.21) 5677.94,2782.21 5709.25,2750.89 v2(5709.25,2317.64) 5713.4,2313.5 v2(5713.4,2202.58)
  Int3 (Signal) w20: v2(1552.33,1953.71) 1552.33,766.48 1625.41,693.4 v2(1913.04,693.4) 1913.04,354.53 1886.19,327.69 1798.98,327.69 J14.2@1796.4,325.1 ; J14.2@1787.5,327.69 J14.2@1796.4,327.69 ; v2(2336.34,95.6) 2336.88,95.6 2340.3,99.02 3823.34,99.02 3851.21,71.14 3857.08,71.14 v2@3857.7,70.53 ; v2(2703.17,2780.14) 2791.39,2691.92 v2(2791.39,2371.59) ; v2(4195.72,2765.39) 4288,2673.11 v2(4288,2359.98)
  Int1 (PGND) w20: v2(3858.62,70.14) 3916.65,128.18 4016.59,128.18 v2(4074.12,70.64) 4117.54,114.06 4289.29,114.06 ; v2(4294.37,70.64) 4293.6,71.41 4293.6,109.74 4289.29,114.06 ; v2(4989.84,62.4) 4989.84,62.94 4976.96,75.82 4976.96,86.27 4949.17,114.06 4289.29,114.06
  Bottom Layer w10: 4450.01,1920.26 4457.2,1920.26 4462.09,1925.15 5568.55,1925.15 5583.4,1940 5583.4,2085.83 5591.83,2094.26 5591.83,2144.62 5623.48,2176.27 5689.92,2176.27 5713.4,2199.75 v2(5713.4,2202.58)
  Bottom Layer w20: v2(1517.6,2268.82) 1518.14,2268.82 1522.45,2264.51 1540.62,2264.51 1552.33,2252.79 v2(1552.33,1953.71) 1552.33,1867.81 1673.52,1746.62 2753.97,1746.62 2797.24,1789.89 4283.82,1789.89 ; J14.2@1812.79,321.15 1954.5,320.11 1998.14,276.47 ; v2(1989.99,95.71) 1990,276.47 2315.42,276.47 2336.34,255.55 v2(2336.34,95.6) ; 2791.39,1784.04 v2(2791.39,2371.59) ; v2(4288,2359.98) 4287.61,2359.6 4287.61,2328.01 4266.26,2306.65 4266.26,2149.71 4280.4,2135.58 4280.4,1793.31 4283.82,1789.89 ; 4450.01,1920.26 4319.65,1789.89 4283.82,1789.89
8V: J15.2 L4.1 | length 220.5
  Top Layer w50: J15.2@1790,1050.25 1792.86,1047.39 1792.86,1003.78 1830.84,965.81 L4.1@1950,965.81
8VA: C22.1 C27.1 C29_1.1 C29_2.1 C29_3.1 C29_4.1 C65.1 C67.1 C83.2 C86.1 C89.1 C91.1 C98.2 C104.2 C124.2 C128.1 C129.2 L4.2 R34_1.1 R34_2.1 R34_3.1 R34_4.1 R207.1 U4.6 U7_1.8 U7_2.8 U7_3.8 U7_4.8 U12.6 U16.8 U18.3 U20.8 U22.8 U26.16 U27.16 U28.8 U29.6 U30.6 | length 15162.6
  Top Layer w10: C29_4.1@1369.56,1963.89 1375.69,1963.89 1413.99,2002.2 U7_4.8@1425.8,2002.2 ; v2(2669.99,569.86) 2693.54,593.41 U28.8@2727.59,593.41 2727.59,622.03 C128.1@2726.69,622.93 ; v2(2692.25,1495.06) 2693.86,1496.67 2693.86,1501.12 2711.7,1518.95 U26.16@2786.82,1518.95 2788.3,1518.95 2792.16,1522.81 C124.2@2792.16,1557.69 ; C29_3.1@2763.14,1945.75 2767.08,1945.75 2773.89,1952.56 2773.89,1956.5 2804.4,1987.01 ; C129.2@2925.19,1306.7 2925.19,1343.72 2929.05,1347.58 U27.16@2929.76,1347.58 2977.36,1347.58 2994.96,1365.17 v2(2996.54,1365.17) ; v2(3223.36,1153.86) 3318.82,1153.86 3342.64,1130.04 3342.64,1067.69 3338.78,1063.83 3338.78,1062.85 3325.08,1049.14 R207.1@3324.09,1049.14 ; C29_2.1@4263.69,1934.14 4304.94,1975.4 4318.94,1975.4 U7_2.8@4322.8,1979.26 ; C104.2@4730.43,1573.12 4735.43,1578.12 4735.43,1631.82 U22.8@4738.18,1634.58 4769.3,1634.58 v2(4770.75,1633.12) ; C98.2@5270.92,1580.41 5270.92,1588.44 v2(5271.68,1589.2) ; C98.2@5272.44,1588.44 5270.92,1589.96 5270.92,1637.76 U20.8@5273.21,1640.05 ; R34_1.1@5639.96,2022.99 5636.02,2022.99 5615.02,2001.99 5615.02,2000.44 5599.72,1985.14 v2(5559.53,1985.14) 5559.53,1922.76 5582.04,1900.25 5687.75,1900.25 5687.75,1915.65 ; U7_1.8@5750.8,1975.26 5738.99,1975.26 5700.69,1936.96 5694.56,1936.96 C29_1.1@5687.75,1930.14 5687.75,1915.65 ; U29.6@5791.06,1590.74 5837.6,1590.74 C65.1@5839.5,1588.83 ; U29.6@5791.06,1593.65 5787.2,1597.51 5766.2,1597.51 5757.51,1606.19 5757.51,1669.16 5778.47,1690.12 5778.47,1717.67 5761.02,1735.11 5761.02,1771.51 ; C67.1@5848.1,1762.94 5848.1,1764.7 5841.29,1771.51 U30.6@5796.81,1771.51 5761.02,1771.51 ; C22.1@6117.06,1579.02 6115.24,1580.85 U4.6@6071.25,1580.85 6067.39,1584.71 6046.39,1584.71 6035.66,1595.44 6035.66,1643.03 6046.39,1653.76 6052.01,1653.76 6067.39,1669.14 6067.39,1701.31 6038.57,1730.13 6038.57,1771.57 6039.63,1772.63 ; C27.1@6137.31,1775.07 6131.01,1768.77 U12.6@6072.11,1768.77 6068.25,1772.63 6039.63,1772.63 ; 5687.75,1915.65 5732.4,1871 5732.4,1863 5739.94,1855.46 5747.94,1855.46 5761.02,1842.37 ; 5761.02,1771.51 5761.02,1842.37 ; 5761.02,1842.37 5769.9,1842.37 5782.99,1855.46 5828.52,1855.46 5834.36,1849.61 5879.89,1849.61 5915.66,1885.38 6006.56,1885.38 6038.57,1853.38 6038.57,1781.31 6039.63,1780.25 6039.63,1772.63
  Top Layer w20: v2(1838.31,1326.03) 1842.46,1321.88 1842.46,1265.26 1854.17,1253.54 v2(1910.96,1253.54) ; L4.2@1950,798.48 2022.66,798.48 2035,810.82 v2(2035,886.44) 2036.89,888.33 2088.94,888.33 C83.2@2090,887.26 2091.79,885.47 2211.51,885.47 U18.3@2213.31,883.68 2333.77,883.68 v2(2544.18,673.27) ; U7_3.8@2810.78,1989.73 2853.44,1989.73 2855.95,1992.24 v2(2856.49,1992.24)
  Int3 (Signal) w10: v2(2995.87,1251.34) 2996.54,1252 v2(2996.54,1365.17) ; v2(4770.75,1633.12) 4875.68,1633.12 5002.17,1506.63 5019.28,1506.63 5034.38,1491.53 5034.38,1431.99 5040.24,1426.13 5198.32,1426.13 5271.68,1499.49 v2(5271.68,1589.2)
  Int3 (Signal) w20: v2(1360.78,1957.08) 1337.85,1957.08 1315.11,1979.82 1315.11,2047.58 1315.65,2048.12 1316.03,2048.12 1316.71,2047.44 1563.36,2047.44 1602.24,2008.56 1602.24,1920.53 v2(1602.62,1920.14) 1602.62,1361.36 1637.95,1326.03 v2(1838.31,1326.03) v2@1910.8,1253.54 ; v2(1910.96,1253.54) 2039.88,1253.54 2120,1173.42 2120,917.33 2089.1,886.44 v2(2035,886.44) ; v2@2660.77,1638.04 2660.77,1709.87 v2(2756.04,1805.14) ; v2(2715.35,2038.6) 2760.03,2038.6 2806.39,1992.24 v2(2856.49,1992.24) ; v2(4213.92,2026.99) 4250,1990.92 4250,1981.08 4251.52,1979.56 v2(4251.52,1934.14) 4251.52,1870.34 4278.78,1843.08 v2(4310.09,1843.08)
  Int1 (PGND) w10: v2(2692.25,1495.06) 2733.23,1536.04 2979.29,1536.04 2980.79,1537.54 3024.97,1537.54 3043.73,1518.78 3268.03,1518.78 3323.33,1574.07 3742.55,1574.07 4008.6,1308.02 4603.65,1308.02 4754.1,1458.47 4754.1,1616.47 v2(4770.75,1633.12)
  Bottom Layer w10: v2(2544.18,673.27) 2546.01,671.44 2546.01,658.34 2634.49,569.86 v2(2669.99,569.86) ; v2(2660.75,1638.02) 2647.59,1624.86 2647.59,1516.71 2669.24,1495.06 v2(2692.25,1495.06) 2694.55,1497.36 2734.42,1497.36 2765.12,1528.05 2858.89,1528.05 2875.72,1511.22 2875.72,1381 2891.54,1365.17 v2(2996.54,1365.17) ; 2907.3,1870.14 3005.98,1870.14 3063.36,1812.76 3920.62,1812.76 3931.86,1824.01 ; v2(2995.87,1251.34) 3149.92,1251.34 3221.4,1179.86 3221.4,1155.82 v2(3223.36,1153.86) ; 4408.39,1941.38 4440,1972.98 4675.14,1972.98 4703.99,1944.13 5553.67,1944.13 5559.53,1949.99 v2(5559.53,1985.14)
  Bottom Layer w20: v2(1602.62,1920.14) 1602.62,1870.4 1698.52,1774.5 2724.86,1774.5 2755.5,1805.14 v2(2756.04,1805.14) ; v2(2715.35,2038.6) 2756.04,1997.9 v2@2756.04,1811.86 ; v2(2856.49,1992.24) 2856.49,1991.7 2881.69,1966.5 2881.69,1895.75 2907.3,1870.14 ; 3931.86,1824.01 4240,1824.01 4251.72,1835.73 4251.72,1933.95 v2(4251.52,1934.14) ; v2(4310.09,1843.08) 4408.39,1941.38
  other v2: 1315.11,2048.5
-8VA: C25.2 C33_1.1 C33_2.1 C33_3.1 C33_4.1 C64.2 C66.2 C71.2 C99.2 C105.2 C127.2 C130.2 J17.1 R27_1.1 R27_2.1 R27_3.1 R27_4.1 R241.2 U4.2 U4.4 U7_1.4 U7_2.4 U7_3.4 U7_4.4 U12.2 U12.4 U20.4 U22.4 U26.7 U27.7 U29.2 U29.4 U30.2 U30.4 | length 12088.8
  Top Layer w10: U7_4.4@1528.16,2078.97 1528.16,2107.91 C33_4.1@1528,2108.08 1528,2183.81 1542.46,2198.28 1725.86,2198.28 1731.71,2192.42 1731.71,2071.05 ; R27_4.1@1635.28,2015.14 1639.21,2015.14 1646.02,2021.96 1646.02,2025.89 1688.87,2068.74 1729.4,2068.74 1731.71,2071.05 ; v2(1740,1904.18) 1740,2000.6 1733.87,2006.73 1733.87,2027.45 1731.71,2029.61 1731.71,2071.05 ; v2(2492.08,1347.69) 2494.04,1347.69 2511.77,1365.41 U26.7@2558.48,1365.41 ; v2(2928.47,2096.67) 2928.56,2096.58 U7_3.4@2928.56,2067.64 ; U27.7@3158.11,1501.12 3213.9,1501.12 3235.05,1522.27 C130.2@3238.99,1522.27 3241.12,1524.4 3241.12,1546.72 3246.98,1552.58 3337.14,1552.58 ; v2(3216.74,1428.73) 3235.14,1410.33 3310.36,1410.33 3316.22,1416.19 3316.22,1531.66 3337.14,1552.58 ; v2(4042.61,1630.72) 3942.56,1630.72 3916.02,1657.26 3755.85,1657.26 3719.61,1621.02 3719.61,1608.39 3713.75,1602.53 3387.09,1602.53 3337.14,1552.58 ; C33_2.1@4425,2085.14 C33_2.1@4425.16,2084.98 ; U7_2.4@4425.16,2056.03 C33_2.1@4425.16,2084.98 ; v2(4454.9,2080.83) 4452.74,2082.99 4427.15,2082.99 C33_2.1@4425.16,2084.98 ; v2@4454.9,2085.14 4561.31,2085.14 4590.42,2056.03 4590.42,2002.25 4577.32,1989.14 R27_2.1@4552.23,1989.14 ; U22.4@4840.54,1711.35 4852.35,1711.35 U22.4@4859.13,1718.12 ; v2(4875.07,1748.77) 4872.78,1746.47 4872.78,1731.77 U22.4@4859.13,1718.12 ; C105.2@4921.8,1718.12 U22.4@4859.13,1718.12 ; U20.4@5375.58,1716.82 5376.94,1718.18 5412.15,1718.18 5429.36,1735.4 v2(5431.71,1735.4) 5434,1733.1 5442.04,1733.1 5453.36,1721.78 C99.2@5457.3,1721.78 5461.23,1721.78 5470.92,1731.47 5470.92,1733.93 5534.14,1797.15 v2@5664.93,1797.15 ; 5659.02,1754.03 5659.02,1786.5 5664.93,1792.41 v2@5664.93,1797.15 ; C66.2@5688.12,1517.46 5688.32,1517.65 U29.4@5688.32,1565.14 ; U29.4@5688.7,1568.06 5684.84,1571.91 5663.84,1571.91 5655.15,1580.6 5655.15,1631.78 ; U29.2@5688.7,1619.24 5684.84,1623.1 5663.84,1623.1 5655.15,1631.78 ; U30.2@5694.45,1797.1 5666.45,1797.12 v2@5664.93,1797.15 ; C71.2@5697.83,1703.3 5694.45,1706.68 U30.4@5694.45,1745.92 5690.59,1749.78 5661.49,1749.78 5659.02,1752.25 5655.15,1748.38 5655.15,1631.78 ; C33_1.1@5853,2081.14 5853.16,2080.98 U7_1.4@5853.16,2052.03 5896.76,2052.03 5913.49,2068.77 6050,2068.77 6061.38,2057.39 6061.38,2000.37 6046.16,1985.14 6035.66,1985.14 ; 5944.89,1790.5 5936.2,1781.82 5936.2,1749.04 5938.2,1747.04 ; U4.2@5968.88,1606.44 5965.03,1610.3 5944.02,1610.3 5939.68,1614.64 ; U12.4@5969.75,1743.18 5965.89,1747.04 5938.2,1747.04 ; U12.2@5969.75,1794.36 v2@5931.17,1794.36 ; C25.2@5972.06,1507.65 5968.88,1510.83 U4.4@5968.88,1555.26 5965.03,1559.12 5944.03,1559.12 5935.34,1567.8 5935.34,1610.3 5939.68,1614.64 ; C64.2@5977.31,1696.56 5971.98,1691.23 5944.06,1691.23 5938.2,1697.09 ; R27_1.1@5980.23,1985.14 6035.66,1985.14 ; v2(6062.52,1910.86) 6033.87,1939.51 6033.87,1983.36 6035.66,1985.14 ; v2(5931.13,1794.32) v2@5931.17,1794.36 ; 5938.2,1697.09 5938.2,1747.04 ; 5938.2,1697.09 5935.34,1694.23 5935.34,1618.98 5939.68,1614.64
  Int3 (Signal) w10: v2(2722.59,1829.02) 2922.61,1829.02 2928.47,1834.88 v2(2928.47,2096.67) ; v2(3055.63,1161.52) 3055.63,1394.61 3096.54,1435.52 v2@3208.45,1435.52 ; v2(3260.81,1899.02) 3260.81,1797.76 3287.47,1771.11 4008.03,1771.11 4043.92,1735.23 4043.92,1632.03 v2(4042.61,1630.72) ; v2(4445.31,1657.68) 4445.31,2068.97 4454.9,2078.56 v2(4454.9,2080.83) ; v2(5666.43,1797.15) 5798.87,1797.15 5827.28,1825.57 5827.28,1906.87 5840.55,1920.14 5877.52,1920.14 5877.63,1920.25 5886.11,1920.25 v2(5888.41,1922.55)
  Int1 (PGND) w10: v2(4445.31,1657.68) 4448.56,1657.68 4460.98,1645.26 4581.22,1645.26 4593.5,1657.55 4844.75,1657.55 4875.07,1687.87 v2(4875.07,1748.77) 4899.57,1773.26 5022.62,1773.26 5051.22,1744.67 5051.22,1719.09 5063.12,1707.19 5083.69,1707.19 5084.43,1707.94 5401,1707.94 5428.46,1735.4 v2(5431.71,1735.4)
  Bottom Layer w10: v2(1740,1904.18) 1740,1833.02 1767.87,1805.14 2698.71,1805.14 v2(2722.59,1829.02) ; v2(2928.47,2096.67) 2928.47,2078.69 3007.19,1999.97 3054.85,1999.97 v2(3055.63,2000.75) 3076.47,1979.91 3076.47,1917.57 3095.02,1899.02 v2(3260.81,1899.02) ; v2(4042.61,1630.72) 4418.36,1630.72 v2(4445.31,1657.68) ; v2(5931.13,1794.32) 5931.98,1795.18 5931.98,1878.97 v2(5888.41,1922.55) 5889.88,1924.02 6046.11,1924.02 6059.27,1910.86 v2(6062.52,1910.86)
  Bottom Layer w20: v2(2492.08,1347.69) 2492.08,1327.09 2480.36,1315.37 2211.99,1315.37 2210.76,1314.14 2187.27,1314.14 2021.46,1148.32 J17.1@2021.46,1050.23 2093.08,1050.23 2257.28,1214.43 2689.72,1214.43 2764,1140.14 3033.71,1140.14 3055.08,1161.52 v2(3055.63,1161.52)
ADC_REF: C62.1 R106.2 U10.42 | length 1397.8
  Top Layer w10: U10.42@5941.46,1004.67 5941.54,1004.75 5984.61,1004.75 6035,1055.14 v2(6071.38,1055.14)
  Bottom Layer w10: v2(4926.34,879.49) 4942.61,863.21 5297.08,863.21 5424.01,990.14 6033.08,990.14 6071.38,1028.44 v2(6071.38,1055.14)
